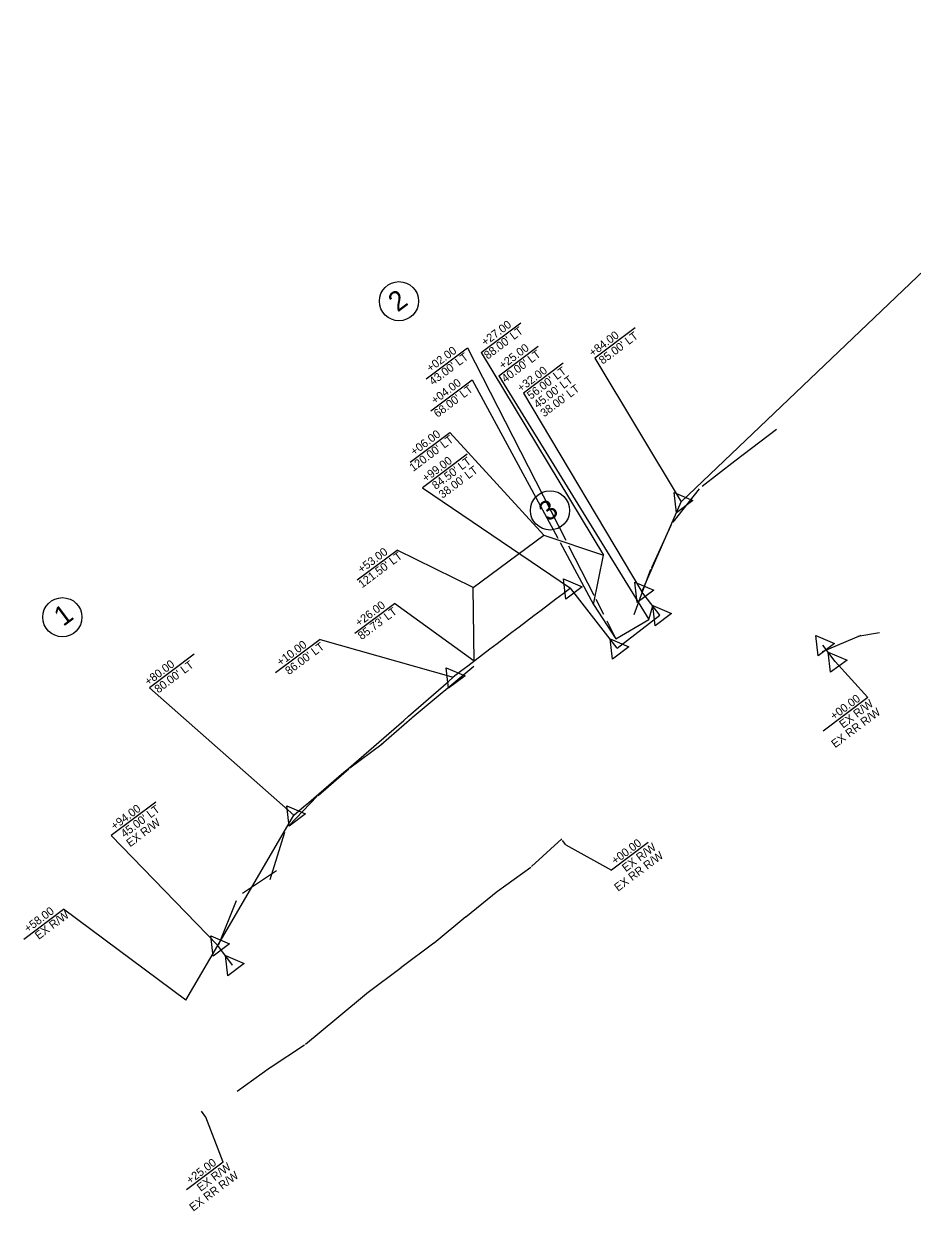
# Model space of a CAD drawing. Extents: x 2187066 to 2190381, y 630308 to 634921.
# Drawn here: x 2187066 to 2187609, y 630308 to 631034 of the extents above; entities that cross this region are included whole.
import ezdxf

# ---------------------------------------------------------------- set-up
doc = ezdxf.new("R2010")
doc.units = 0
for name, color, linetype in [('Old_Level_1', 7, 'Continuous'), ('Prop Dimension', 7, 'Continuous'), ('Prop Horizontal Alignment', 7, 'Continuous'), ('Prop Horizontal Alignment Curve and Spiral Data', 7, 'Continuous'), ('Prop Horizontal Alignment Tick Large', 7, 'Continuous'), ('Prop Horizontal Alignment Tick Small', 7, 'Continuous'), ('Prop Lane Lines', 7, 'Continuous'), ('Raster_Level_3', 7, 'Continuous'), ('Scratch_Level_3', 7, 'Continuous')]:
    doc.layers.add(name, color=color, linetype=linetype)

msp = doc.modelspace()

# ---------------------------------------------------------------- linework, layer by layer
at = {"layer": 'Old_Level_1'}
for p, q in [((2187467.92, 630741.67), (2187774.33, 631034.12)), ((2187443.91, 630686.74), (2187467.92, 630741.67)), ((2187428.68, 630652.19), (2187400.13, 630688.89)), ((2187454.9, 630672.49), (2187443.91, 630686.74)), ((2187562.14, 630644.07), (2187554.55, 630654.1)), ((2187184.44, 630470.44), (2187230.95, 630550.07)), ((2187193.52, 630458.42), (2187184.44, 630470.44))]:
    msp.add_line(p, q, dxfattribs=at)
for centre, radius, start, end in [((2192446.71, 623976.72), 8397.68, 126.937842, 127.55171), ((2181083.2, 637757.94), 9473.56, 310.461597, 311.24167)]:
    msp.add_arc(centre, radius, start, end, dxfattribs=at)
at = {"layer": 'Prop Horizontal Alignment'}
for p, q in [((2187439.74, 630848.14), (2187415.07, 630829.65)), ((2187395.7, 630826.44), (2187371.35, 630808.18)), ((2187415.07, 630829.65), (2187467.92, 630741.67)), ((2187371.35, 630808.18), (2187443.91, 630686.74)), ((2187336.94, 630770.85), (2187309.62, 630750.36)), ((2187309.62, 630750.36), (2187400.13, 630688.89)), ((2187428.68, 630652.19), (2187454.9, 630672.49)), ((2187247.1, 630657.6), (2187219.77, 630637.12)), ((2187247.1, 630657.6), (2187328.51, 630634.44)), ((2187170.02, 630648.53), (2187142.69, 630628.04)), ((2187562.14, 630644.07), (2187582.11, 630621.97)), ((2187142.69, 630628.04), (2187230.95, 630550.07)), ((2187582.11, 630621.97), (2187554.78, 630601.49)), ((2187146.55, 630558.02), (2187119.22, 630537.54)), ((2187184.44, 630470.44), (2187119.22, 630537.54))]:
    msp.add_line(p, q, dxfattribs=at)
at = {"layer": 'Prop Horizontal Alignment Curve and Spiral Data'}
for p, q in [((2187500.77, 630766.83), (2187526.19, 630786.22)), ((2187480.78, 630751.26), (2187500.69, 630766.77)), ((2187462.88, 630729.25), (2187479.1, 630749.61)), ((2187461.62, 630727.2), (2187449.7, 630701.31)), ((2187439.09, 630672.78), (2187449.41, 630700.61)), ((2187554.41, 630650.2), (2187578.06, 630660.19)), ((2187575.87, 630659.54), (2187589.17, 630661.84)), ((2187303.31, 630609.77), (2187341.08, 630641.24)), ((2187284.45, 630593.3), (2187303.14, 630609.62)), ((2187265.18, 630579), (2187285.06, 630593.79)), ((2187245.88, 630562.2), (2187264.57, 630578.51)), ((2187227.86, 630543.61), (2187245.26, 630561.62)), ((2187216.41, 630510.82), (2187225.51, 630539.67)), ((2187199.66, 630502.43), (2187220.43, 630516.15)), ((2187185.06, 630470.99), (2187195.9, 630497.83))]:
    msp.add_line(p, q, dxfattribs=at)
at = {"layer": 'Prop Horizontal Alignment Tick Large'}
for p, q in [((2187376.25, 630518.7), (2187394.86, 630535.6)), ((2187355.54, 630503.56), (2187375.84, 630518.36)), ((2187336.19, 630487.98), (2187355.73, 630503.71)), ((2187316.86, 630472.05), (2187336.23, 630488.01)), ((2187296.51, 630456.94), (2187316.66, 630471.9)), ((2187276.53, 630441.83), (2187296.54, 630456.96)), ((2187257.33, 630425.98), (2187276.7, 630441.97)), ((2187238.02, 630409.94), (2187257.34, 630425.99)), ((2187216.55, 630395.8), (2187237.57, 630409.6)), ((2187196.41, 630381.27), (2187216.73, 630395.93))]:
    msp.add_line(p, q, dxfattribs=at)
at = {"layer": 'Prop Horizontal Alignment Tick Small'}
for p, q in [((2187345.46, 630832.97), (2187369.74, 630851.17)), ((2187311.9, 630817.04), (2187337.14, 630835.96)), ((2187337.14, 630835.96), (2187397.27, 630718.17)), ((2187345.46, 630832.97), (2187420.36, 630709)), ((2187356.28, 630818.79), (2187380.49, 630836.95)), ((2187314.71, 630797.35), (2187340.14, 630816.42)), ((2187340.14, 630816.42), (2187392.39, 630719.51)), ((2187356.28, 630818.79), (2187448.11, 630669.77)), ((2187302.09, 630765.98), (2187326.38, 630784.19)), ((2187326.38, 630784.19), (2187383.95, 630721.27)), ((2187393.81, 630716.87), (2187414.24, 630678.96)), ((2187398.97, 630714.84), (2187414.38, 630684.64)), ((2187269.81, 630693.98), (2187294.09, 630712.19)), ((2187340.63, 630689.31), (2187294.09, 630712.19)), ((2187268.33, 630661.37), (2187292.61, 630679.57)), ((2187341.34, 630644.28), (2187292.61, 630679.57)), ((2187415.61, 630682.24), (2187420.32, 630673.02)), ((2187422.37, 630669), (2187427.99, 630657.98)), ((2187397.32, 630532.02), (2187425.3, 630516.41)), ((2187447.79, 630533.27), (2187425.3, 630516.41)), ((2187065.79, 630474.27), (2187090.07, 630492.48)), ((2187164.82, 630436.9), (2187090.07, 630492.48)), ((2187187.78, 630337.77), (2187177.23, 630365.33)), ((2187187.78, 630337.77), (2187165.28, 630320.91))]:
    msp.add_line(p, q, dxfattribs=at)
at = {"layer": 'Prop Lane Lines'}
for p, q in [((2187295.29, 630864.41), (2187295.29, 630864.41)), ((2187387.67, 630736.48), (2187387.67, 630736.48)), ((2187089.41, 630671.13), (2187089.41, 630671.13))]:
    msp.add_line(p, q, dxfattribs=at)
for centre in [(2187295.29, 630864.41), (2187387.67, 630736.48), (2187089.41, 630671.13)]:
    msp.add_circle(centre, 12, dxfattribs=at)
at = {"layer": 'Raster_Level_3'}
for p, q in [((2187467.92, 630741.67), (2187467.92, 630741.67)), ((2187400.13, 630688.89), (2187400.13, 630688.89)), ((2187443.91, 630686.74), (2187443.91, 630686.74)), ((2187454.9, 630672.49), (2187454.9, 630672.49)), ((2187428.68, 630652.19), (2187428.68, 630652.19)), ((2187554.55, 630654.1), (2187554.55, 630654.1)), ((2187562.14, 630644.07), (2187562.14, 630644.07)), ((2187328.51, 630634.44), (2187328.51, 630634.44)), ((2187230.95, 630550.07), (2187230.95, 630550.07)), ((2187184.44, 630470.44), (2187184.44, 630470.44)), ((2187193.52, 630458.42), (2187193.52, 630458.42))]:
    msp.add_line(p, q, dxfattribs=at)
for points in [[(2187465.08, 630735.04), (2187463.6, 630747.43), (2187475.08, 630742.54)], [(2187397.29, 630682.26), (2187395.81, 630694.65), (2187407.29, 630689.76)], [(2187441.06, 630680.11), (2187439.59, 630692.5), (2187451.07, 630687.61)], [(2187452.06, 630665.86), (2187450.58, 630678.25), (2187462.06, 630673.36)], [(2187425.84, 630645.56), (2187424.36, 630657.95), (2187435.84, 630653.05)], [(2187551.71, 630647.47), (2187550.23, 630659.86), (2187561.71, 630654.97)], [(2187559.3, 630637.44), (2187557.82, 630649.83), (2187569.3, 630644.94)], [(2187325.67, 630627.81), (2187324.19, 630640.2), (2187335.67, 630635.31)], [(2187228.11, 630543.44), (2187226.63, 630555.83), (2187238.11, 630550.94)], [(2187181.59, 630463.81), (2187180.12, 630476.2), (2187191.6, 630471.31)], [(2187190.68, 630451.79), (2187189.2, 630464.18), (2187200.68, 630459.29)]]:
    msp.add_lwpolyline(points, close=True, dxfattribs=at)
at = {"layer": 'Scratch_Level_3'}
for p, q in [((2187340.63, 630689.31), (2187383.95, 630721.27)), ((2187383.95, 630721.27), (2187420.36, 630709)), ((2187414.24, 630678.96), (2187420.36, 630709)), ((2187341.34, 630644.28), (2187340.63, 630689.31)), ((2187414.24, 630678.96), (2187427.99, 630657.98)), ((2187448.11, 630669.77), (2187450.62, 630678.03)), ((2187427.99, 630657.98), (2187448.11, 630669.77)), ((2187397.32, 630532.02), (2187395.22, 630534.65)), ((2187164.82, 630436.9), (2187184.44, 630470.44)), ((2187177.23, 630365.33), (2187174.4, 630369.1))]:
    msp.add_line(p, q, dxfattribs=at)

# ---------------------------------------------------------------- texts
at = {"layer": 'Prop Dimension'}
for s, p in [('2', (2187294.48, 630857.4)), ('3', (2187386.54, 630729.23)), ('1', (2187089.97, 630665.15))]:
    msp.add_text(s, height=12, rotation=36.85926, dxfattribs=at).set_placement(p)
at = {"layer": 'Prop Horizontal Alignment'}
for s, p in [('+84.00', (2187413.79, 630830.26)), ("85.00' LT", (2187419.89, 630825.59)), ('+32.00', (2187369.94, 630808.7)), ("56.00' LT", (2187375.97, 630804.13)), ("45.00' LT", (2187380.03, 630798.7)), ("38.00' LT", (2187384.1, 630793.33)), ('+99.00', (2187311.75, 630753.54)), ("84.50' LT", (2187317.79, 630748.96)), ("38.00' LT", (2187321.87, 630743.51)), ('+10.00', (2187222.86, 630641.01)), ("86.00' LT", (2187228.01, 630635.62)), ('+80.00', (2187141.99, 630629.1)), ("80.00' LT", (2187148.1, 630624.42)), ('+00.00', (2187561.4, 630608.03)), ('EX R/W', (2187566.88, 630602.96)), ('EX RR R/W', (2187562.03, 630590.95)), ('+94.00', (2187121.35, 630540.71)), ("45.00' LT", (2187127.42, 630536.09)), ('EX R/W', (2187130.83, 630530.32))]:
    msp.add_text(s, height=5, rotation=36.85926, dxfattribs=at).set_placement(p)
at = {"layer": 'Prop Horizontal Alignment Tick Small'}
for s, p in [('+27.00', (2187348, 630836.75)), ("88.00' LT", (2187349.59, 630828.64)), ('+25.00', (2187358.76, 630822.52)), ('+02.00', (2187314.48, 630820.84)), ("43.00' LT", (2187316.08, 630812.72)), ("40.00' LT", (2187360.35, 630814.41)), ('+04.00', (2187317.28, 630801.15)), ("68.00' LT", (2187318.88, 630793.03)), ("120.00' LT", (2187304.02, 630760)), ('+06.00', (2187304.64, 630769.76)), ('+53.00', (2187272.36, 630697.77)), ("121.50' LT", (2187272.7, 630688.72)), ('+26.00', (2187270.87, 630665.15)), ("85.73' LT", (2187272.46, 630657.04)), ('+00.00', (2187427.57, 630519.67)), ('EX R/W', (2187434.04, 630515.15)), ('EX RR R/W', (2187429.26, 630503.19)), ('+58.00', (2187068.33, 630478.05)), ('EX R/W', (2187074.96, 630473.72)), ('+25.00', (2187167.55, 630324.17)), ('EX R/W', (2187174.03, 630319.65)), ('EX RR R/W', (2187169.4, 630307.49))]:
    msp.add_text(s, height=5, rotation=36.85926, dxfattribs=at).set_placement(p)

doc.saveas('drawing.dxf')
